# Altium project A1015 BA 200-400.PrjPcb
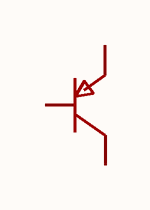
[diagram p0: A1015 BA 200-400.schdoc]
1 sheet, 1 parts. Net scope: global (net labels, ports and power ports of the same name join across sheets).

## Sheet A1015 BA 200-400.schdoc
size 127 x 101 mm

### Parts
Q?  a1015(range:200-400)  [SOT-23-3_L2.9-W1.6-P1.90-LS2.8-BR]  (value not drawn)

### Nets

Not connected (* = marked no-connect by the designer): Q? 1(B) 2(E) 3(C)

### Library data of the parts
Q? = a1015(range:200-400): 晶体管类型:PNP;集电极电流(Ic):150mA;集射极击穿电压(Vceo):50V;耗散功率(Pd):200mW;直流电流增益(hFE):200;; Manufacturer: CJ(江苏长电/长晶); Symbol: A1015 BA 200-400; AddInBom: yes; ModelId: 89cb27a44ab2466697082bb9fd73a7d0; ModelName: SOT-23-3L_L2.9-W1.6-H1.1-LS2.8-P0.95; ModelTransform: 114.173,110.236,0,90,0,0,0,0,0; type: PNP; Current - Collector(Ic): 150mA; Collector - Emitter Voltage VCEO: 50V; Pd - Power Dissipation: 200mW; DC Current Gain: 200; Transition frequency(fT): 80MHz; Current - Collector Cutoff: 100nA; Vce Saturation(VCE(sat)): 300mV; Emitter-Base Voltage(Vebo): 5V; Number: 1个PNP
